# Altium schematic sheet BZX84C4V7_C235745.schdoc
size 127 x 101 mm
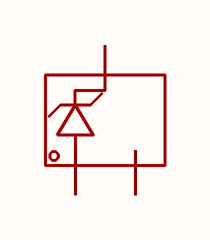
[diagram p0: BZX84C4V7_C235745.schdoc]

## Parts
D?  bzx84c4v7_c235745  [SOT-23-3_L2.9-W1.6-P1.90-LS2.8-BR]  (value not drawn)

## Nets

Not connected (* = marked no-connect by the designer): D? 1 2 3

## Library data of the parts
D? = bzx84c4v7_c235745: 二极管配置:1个独立式;稳压值(标称值):4.7V;稳压值(范围):4.4V~5V;耗散功率(Pd):300mW;; Manufacturer: CJ(江苏长电/长晶); AddInBom: yes; ModelId: 89cb27a44ab2466697082bb9fd73a7d0; ModelName: SOT-23-3L_L2.9-W1.6-H1.1-LS2.8-P0.95; ModelTransform: 114.173,110.236,0,90,0,0,0,0,0; Diode Configuration: 1个独立式; Zener Voltage(Nom): 4.7V; Reverse Leakage Current (Ir): 3uA@2V; Pd - Power Dissipation: 300mW; Impedance(Zzt): 80Ω; Impedance(Zzk): 500Ω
